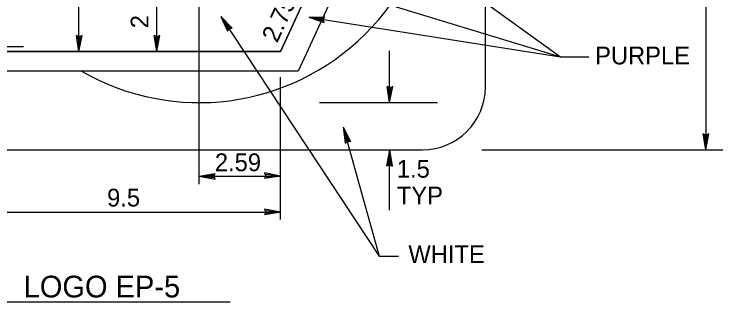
# Model space of a CAD drawing. Extents: x 10268197 to 10269179, y 2141503 to 2142677.
# Drawn here: x 10268795.36 to 10268823.51, y 2142016.12 to 2142027.53 of the extents above; entities that cross this region are included whole.
import ezdxf

# ---------------------------------------------------------------- set-up
doc = ezdxf.new("R2010")
doc.units = 0
for name, color, linetype in [('1', 7, 'Continuous'), ('21', 7, 'Continuous'), ('Default', 7, 'Continuous'), ('TextMisc', 7, 'Continuous'), ('TextShtNo', 7, 'Continuous')]:
    doc.layers.add(name, color=color, linetype=linetype)

msp = doc.modelspace()

# ---------------------------------------------------------------- linework, layer by layer
at = {"layer": '1'}
for p, q in [((10268807.135, 2142033.003), (10268817.055, 2142025.842)), ((10268802.908, 2142030.146), (10268817.055, 2142025.842)), ((10268807.057, 2142027.411), (10268817.055, 2142025.842)), ((10268817.055, 2142025.842), (10268818.188, 2142025.842))]:
    msp.add_line(p, q, dxfattribs=at)
at = {"layer": '21'}
msp.add_line((10268794.221, 2142016.121), (10268803.934, 2142016.121), dxfattribs=at)
at = {"layer": 'Default'}
for p, q in [((10268822.833, 2142044.646), (10268822.833, 2142022.146)), ((10268814.077, 2142024.646), (10268814.077, 2142042.146)), ((10268797.93, 2142026.046), (10268797.93, 2142040.78)), ((10268802.703, 2142020.783), (10268802.703, 2142033.396)), ((10268807.457, 2142029.328), (10268805.941, 2142026.046)), ((10268801.024, 2142026.046), (10268801.024, 2142028.501)), ((10268808.151, 2142028.552), (10268806.635, 2142025.27)), ((10268803.571, 2142027.444), (10268804.021, 2142026.978)), ((10268803.571, 2142027.444), (10268803.836, 2142026.853)), ((10268803.571, 2142027.444), (10268803.871, 2142026.907)), ((10268803.571, 2142027.444), (10268803.958, 2142026.967)), ((10268803.572, 2142027.444), (10268809.863, 2142017.928)), ((10268807.057, 2142027.411), (10268807.702, 2142027.423)), ((10268807.057, 2142027.411), (10268807.667, 2142027.201)), ((10268807.057, 2142027.411), (10268807.651, 2142027.263)), ((10268807.057, 2142027.411), (10268807.668, 2142027.369)), ((10268807.636, 2142027.32), (10268807.702, 2142027.423)), ((10268807.667, 2142027.201), (10268807.636, 2142027.32)), ((10268803.836, 2142026.853), (10268803.901, 2142026.956)), ((10268803.901, 2142026.956), (10268804.021, 2142026.978)), ((10268797.93, 2142026.046), (10268797.83, 2142026.685)), ((10268797.941, 2142026.635), (10268797.83, 2142026.685)), ((10268797.93, 2142026.046), (10268797.888, 2142026.658)), ((10268797.93, 2142026.046), (10268798.054, 2142026.682)), ((10268797.93, 2142026.046), (10268797.994, 2142026.657)), ((10268798.054, 2142026.682), (10268797.941, 2142026.635)), ((10268801.024, 2142026.046), (10268800.923, 2142026.685)), ((10268801.034, 2142026.635), (10268800.923, 2142026.685)), ((10268801.024, 2142026.046), (10268800.981, 2142026.658)), ((10268801.024, 2142026.046), (10268801.147, 2142026.682)), ((10268801.024, 2142026.046), (10268801.087, 2142026.657)), ((10268801.147, 2142026.682), (10268801.034, 2142026.635)), ((10268793.819, 2142026.248), (10268795.727, 2142026.248)), ((10268810.27, 2142024.021), (10268810.27, 2142026.083)), ((10268805.941, 2142026.046), (10268794.692, 2142026.046)), ((10268806.635, 2142025.27), (10268794.335, 2142025.27)), ((10268805.941, 2142019.382), (10268805.941, 2142025.028)), ((10268810.27, 2142024.021), (10268810.17, 2142024.66)), ((10268810.28, 2142024.61), (10268810.17, 2142024.66)), ((10268810.27, 2142024.021), (10268810.228, 2142024.633)), ((10268810.27, 2142024.021), (10268810.394, 2142024.656)), ((10268810.27, 2142024.021), (10268810.334, 2142024.632)), ((10268810.394, 2142024.656), (10268810.28, 2142024.61)), ((10268807.488, 2142024.021), (10268812.175, 2142024.021)), ((10268808.426, 2142023.052), (10268809.863, 2142017.928)), ((10268808.426, 2142023.052), (10268808.718, 2142022.474)), ((10268808.426, 2142023.052), (10268808.504, 2142022.409)), ((10268808.426, 2142023.052), (10268808.553, 2142022.45)), ((10268808.426, 2142023.052), (10268808.655, 2142022.482)), ((10268822.833, 2142022.146), (10268822.732, 2142022.785)), ((10268822.843, 2142022.734), (10268822.732, 2142022.785)), ((10268822.833, 2142022.146), (10268822.791, 2142022.758)), ((10268822.833, 2142022.146), (10268822.956, 2142022.782)), ((10268822.833, 2142022.146), (10268822.897, 2142022.757)), ((10268822.956, 2142022.782), (10268822.843, 2142022.734)), ((10268808.504, 2142022.409), (10268808.597, 2142022.488)), ((10268808.597, 2142022.488), (10268808.718, 2142022.474)), ((10268786.578, 2142022.146), (10268811.577, 2142022.146)), ((10268810.27, 2142022.146), (10268810.148, 2142021.51)), ((10268810.27, 2142022.146), (10268810.207, 2142021.534)), ((10268810.27, 2142019.753), (10268810.27, 2142022.146)), ((10268810.27, 2142022.146), (10268810.372, 2142021.506)), ((10268810.27, 2142022.146), (10268810.314, 2142021.534)), ((10268810.148, 2142021.51), (10268810.261, 2142021.557)), ((10268810.261, 2142021.557), (10268810.372, 2142021.506)), ((10268802.703, 2142021.11), (10268803.342, 2142021.211)), ((10268802.703, 2142021.11), (10268803.315, 2142021.153)), ((10268802.703, 2142021.11), (10268805.941, 2142021.11)), ((10268802.703, 2142021.11), (10268803.338, 2142020.986)), ((10268802.703, 2142021.11), (10268803.314, 2142021.046)), ((10268803.291, 2142021.099), (10268803.342, 2142021.211)), ((10268803.338, 2142020.986), (10268803.291, 2142021.099)), ((10268805.352, 2142021.12), (10268805.302, 2142021.008)), ((10268805.941, 2142021.11), (10268805.302, 2142021.008)), ((10268805.941, 2142021.11), (10268805.306, 2142021.233)), ((10268805.306, 2142021.233), (10268805.352, 2142021.12)), ((10268805.941, 2142021.11), (10268805.328, 2142021.066)), ((10268805.941, 2142021.11), (10268805.33, 2142021.174)), ((10268794.066, 2142019.672), (10268805.941, 2142019.672)), ((10268805.352, 2142019.681), (10268805.302, 2142019.571)), ((10268805.941, 2142019.672), (10268805.302, 2142019.571)), ((10268805.941, 2142019.672), (10268805.306, 2142019.795)), ((10268805.306, 2142019.795), (10268805.352, 2142019.681)), ((10268805.941, 2142019.672), (10268805.328, 2142019.629)), ((10268805.941, 2142019.672), (10268805.33, 2142019.735)), ((10268809.863, 2142017.928), (10268810.62, 2142017.928))]:
    msp.add_line(p, q, dxfattribs=at)
for centre, major_axis, start_param, end_param in [((10268802.702, 2142033.396), (0, 9.375), 2.619545, 5.22594), ((10268811.577, 2142024.646), (0, -2.5), 0, 1.570796)]:
    msp.add_ellipse(centre, major_axis=major_axis, ratio=0.999997, start_param=start_param, end_param=end_param, dxfattribs=at)
at = {"layer": 'TextMisc'}
msp.add_line((10268813.935, 2142022.146), (10268823.511, 2142022.146), dxfattribs=at)
at = {"layer": 'TextShtNo'}
for p, q in [((10268805.941, 2142026.046), (10268807.099, 2142028.552)), ((10268808.151, 2142028.552), (10268806.635, 2142025.27)), ((10268794.692, 2142026.046), (10268805.941, 2142026.046)), ((10268806.635, 2142025.27), (10268794.335, 2142025.27))]:
    msp.add_line(p, q, dxfattribs=at)

# ---------------------------------------------------------------- texts
at = {"layer": '1'}
for s, height, rotation, p in [('2.75', 0.7047, 65.0602, (10268805.804, 2142026.361)), ('2', 0.705, 90, (10268800.69, 2142026.973))]:
    msp.add_text(s, height=height, rotation=rotation, dxfattribs=at).set_placement(p)
for s, height, p in [('PURPLE', 0.7047, (10268818.436, 2142025.539)), ('2.59', 0.7047, (10268803.329, 2142021.303)), ('1.5', 0.7047, (10268810.56, 2142021.044)), ('9.5', 0.7047, (10268799.047, 2142019.901)), ('TYP', 0.7047, (10268810.56, 2142019.987)), ('WHITE', 0.7047, (10268811.018, 2142017.656)), ('LOGO EP-5', 0.8624, (10268795.733, 2142016.294))]:
    msp.add_text(s, height=height, dxfattribs=at).set_placement(p)

doc.saveas('drawing.dxf')
